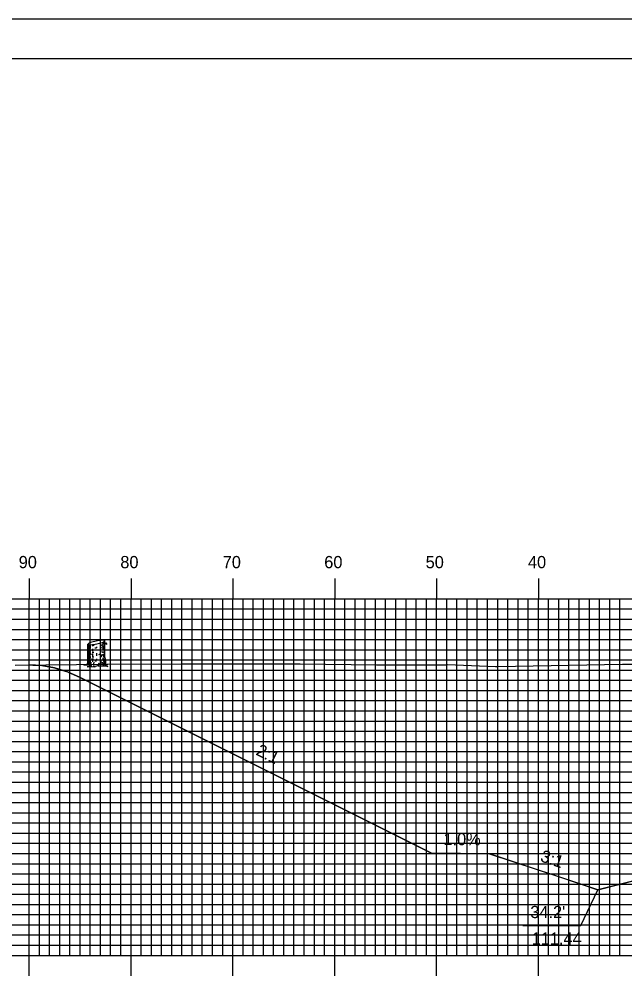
# Model space of a CAD drawing. Extents: x 1767694 to 1768037, y 442591 to 442811.
# Drawn here: x 1767768.5 to 1767827.9, y 442716.2 to 442810.5 of the extents above; entities that cross this region are included whole.
import ezdxf

# ---------------------------------------------------------------- set-up
doc = ezdxf.new("R2010")
doc.units = 0
for name, color, linetype in [('ANNOTATION', 7, 'Continuous'), ('BORDER', 7, 'Continuous'), ('D_Roadway_Centerline', 7, 'Continuous'), ('D_Roadway_SlopeLines', 7, 'Continuous'), ('H_V ANNOTATION', 7, 'Continuous'), ('M_Trees_Conifer_Pay', 7, 'Continuous'), ('MAJOR', 7, 'Continuous'), ('MINOR', 7, 'Continuous'), ('PLOT BOUNDARY', 7, 'Continuous'), ('S_Roadway_Centerline', 7, 'Continuous')]:
    doc.layers.add(name, color=color, linetype=linetype)

msp = doc.modelspace()

# ---------------------------------------------------------------- linework, layer by layer
at = {"layer": 'ANNOTATION'}
msp.add_lwpolyline([(1767817.92, 442721.594), (1767823.612, 442721.594), (1767825.276, 442725.102)], dxfattribs=at)
at = {"layer": 'BORDER'}
msp.add_lwpolyline([(1767709.85, 442596.665), (1768029.85, 442596.665), (1768029.85, 442806.665), (1767709.85, 442806.665)], close=True, dxfattribs=at)
at = {"layer": 'D_Roadway_Centerline'}
msp.add_lwpolyline([(1767769.449, 442747.172), (1767769.818, 442747.152), (1767770.699, 442747.105), (1767771.95, 442746.879), (1767772.422, 442746.733), (1767773.2, 442746.493), (1767774.449, 442745.948), (1767808.936, 442728.705), (1767808.94, 442728.703), (1767814.641, 442728.646), (1767814.645, 442728.646), (1767821.607, 442726.325), (1767825.276, 442725.102), (1767825.277, 442725.103), (1767829.276, 442726.102)], dxfattribs=at)
at = {"layer": 'D_Roadway_SlopeLines'}
for points in [[(1767814.645, 442728.646), (1767808.94, 442728.703), (1767774.449, 442745.948), (1767773.2, 442746.493), (1767771.95, 442746.879), (1767770.699, 442747.105), (1767769.449, 442747.172)], [(1767825.276, 442725.102), (1767814.645, 442728.646)], [(1767839.449, 442728.646), (1767825.276, 442725.102)]]:
    msp.add_lwpolyline(points, dxfattribs=at)
at = {"layer": 'M_Trees_Conifer_Pay'}
for p, q in [((1767775.22, 442747.481), (1767775.22, 442749.203)), ((1767775.267, 442749.165), (1767775.267, 442748.694)), ((1767775.325, 442749.154), (1767775.325, 442749.057)), ((1767775.325, 442748.982), (1767775.325, 442748.778)), ((1767775.451, 442749.146), (1767775.451, 442748.914)), ((1767775.451, 442748.873), (1767775.451, 442748.799)), ((1767775.67, 442749.167), (1767775.67, 442748.999)), ((1767776.076, 442748.935), (1767776.076, 442748.84)), ((1767776.466, 442749.209), (1767776.466, 442749.009)), ((1767776.466, 442748.952), (1767776.466, 442748.863)), ((1767776.695, 442749.405), (1767776.695, 442749.182)), ((1767776.695, 442749.093), (1767776.695, 442749.046)), ((1767776.752, 442748.91), (1767776.701, 442748.85)), ((1767776.812, 442749.466), (1767776.812, 442749.303)), ((1767776.812, 442749.236), (1767776.812, 442749.108)), ((1767776.812, 442748.921), (1767776.812, 442748.585)), ((1767776.884, 442747.891), (1767776.884, 442749.538)), ((1767775.267, 442748.63), (1767775.267, 442748.322)), ((1767775.267, 442748.274), (1767775.267, 442747.782)), ((1767775.325, 442748.721), (1767775.325, 442748.521)), ((1767775.325, 442748.474), (1767775.325, 442748.138)), ((1767775.325, 442748.085), (1767775.325, 442747.949)), ((1767775.451, 442748.396), (1767775.451, 442748.257)), ((1767775.451, 442747.986), (1767775.451, 442747.844)), ((1767775.67, 442748.762), (1767775.67, 442748.525)), ((1767775.67, 442748.28), (1767775.67, 442748.128)), ((1767775.67, 442748.085), (1767775.67, 442747.911)), ((1767776.076, 442748.322), (1767776.076, 442748.247)), ((1767776.076, 442748.223), (1767776.076, 442748.074)), ((1767776.466, 442748.515), (1767776.466, 442748.41)), ((1767776.466, 442748.043), (1767776.466, 442747.897)), ((1767776.695, 442748.711), (1767776.695, 442748.579)), ((1767776.695, 442748.468), (1767776.695, 442748.358)), ((1767776.695, 442748.223), (1767776.695, 442748.081)), ((1767776.812, 442748.548), (1767776.812, 442748.385)), ((1767776.812, 442748.338), (1767776.812, 442748.121)), ((1767776.812, 442748.091), (1767776.812, 442748.016)), ((1767776.812, 442747.976), (1767776.812, 442747.803)), ((1767775.267, 442747.728), (1767775.267, 442747.481)), ((1767775.325, 442747.85), (1767775.325, 442747.471)), ((1767775.451, 442747.582), (1767775.451, 442747.488)), ((1767775.451, 442747.088), (1767775.613, 442747.152)), ((1767775.67, 442747.634), (1767775.67, 442747.481)), ((1767775.888, 442747.024), (1767775.762, 442747.088)), ((1767776.076, 442747.782), (1767776.076, 442747.629)), ((1767776.466, 442747.665), (1767776.466, 442747.576)), ((1767776.695, 442747.854), (1767776.695, 442747.681))]:
    msp.add_line(p, q, dxfattribs=at)
for points in [[(1767776.667, 442748.999), (1767776.636, 442748.914), (1767776.632, 442748.847), (1767776.663, 442748.783)], [(1767776.701, 442749.036), (1767776.737, 442748.962), (1767776.785, 442749.019), (1767776.842, 442749.087), (1767776.935, 442749.281), (1767776.999, 442749.328), (1767777.03, 442749.335)], [(1767776.715, 442748.783), (1767776.752, 442748.91), (1767776.815, 442749.026), (1767776.846, 442749.093), (1767776.915, 442749.24)], [(1767776.93, 442749.269), (1767777.005, 442749.277), (1767777.077, 442749.178)], [(1767775.399, 442748.509), (1767775.393, 442748.604), (1767775.436, 442748.581), (1767775.436, 442748.486)], [(1767776.538, 442748.11), (1767776.55, 442748.033), (1767776.598, 442748.043), (1767776.585, 442748.21)], [(1767776.884, 442747.891), (1767776.935, 442747.629), (1767776.951, 442747.356), (1767777.009, 442747.23), (1767777.145, 442747.2), (1767776.915, 442747.162), (1767776.915, 442747.162), (1767776.92, 442747.115), (1767777.168, 442747.02), (1767776.894, 442747.037), (1767776.538, 442747.057), (1767776.216, 442747.047), (1767776.223, 442747.129), (1767776.075, 442747.047), (1767775.888, 442747.024), (1767775.912, 442746.956), (1767775.644, 442746.999), (1767775.424, 442746.973), (1767775.131, 442746.99), (1767775.42, 442747.047), (1767775.451, 442747.088), (1767775.288, 442747.146), (1767775.051, 442747.156), (1767774.81, 442747.156), (1767775.152, 442747.214), (1767775.193, 442747.294), (1767775.22, 442747.481)], [(1767775.268, 442747.434), (1767775.247, 442747.356), (1767775.226, 442747.261)], [(1767775.346, 442747.413), (1767775.352, 442747.298), (1767775.298, 442747.209), (1767775.288, 442747.146)], [(1767775.508, 442747.44), (1767775.508, 442747.308), (1767775.42, 442747.209)], [(1767775.735, 442747.2), (1767775.802, 442747.294), (1767775.829, 442747.434)], [(1767776.223, 442747.129), (1767776.297, 442747.271), (1767776.307, 442747.372)], [(1767776.474, 442747.498), (1767776.484, 442747.372), (1767776.558, 442747.329)], [(1767776.752, 442747.109), (1767776.737, 442747.247), (1767776.663, 442747.376)], [(1767776.71, 442747.603), (1767776.785, 442747.498), (1767776.789, 442747.325), (1767776.915, 442747.162)], [(1767776.81, 442747.749), (1767776.815, 442747.603), (1767776.863, 442747.535), (1767776.873, 442747.335)]]:
    msp.add_lwpolyline(points, dxfattribs=at)
for centre, radius, start, end in [((1767775.252, 442749.025), 0.0334, 163.94846, 180), ((1767775.252, 442749.025), 0.0334, 180, 196.05154), ((1767775.251, 442749.202), 0.0314, 156.51582, 169.2194), ((1767775.246, 442749.203), 0.0264, 169.2194, 180.03145), ((1767775.242, 442749.203), 0.0226, 180.03145, 191.7194), ((1767775.242, 442749.203), 0.0226, 191.7194, 203.40735), ((1767775.262, 442749.028), 0.0441, 196.05154, 210), ((1767775.271, 442749.193), 0.0527, 146.7194, 156.51582), ((1767775.246, 442749.204), 0.0264, 203.40735, 214.2194), ((1767775.25, 442749.207), 0.0314, 214.2194, 226.92298), ((1767775.278, 442749.037), 0.0624, 210, 228.74941), ((1767775.295, 442749.177), 0.0817, 132.38868, 146.7194), ((1767775.265, 442749.222), 0.0527, 226.92298, 236.7194), ((1767775.28, 442749.247), 0.0817, 236.7194, 251.05013), ((1767775.35, 442749.119), 0.172, 228.74941, 240), ((1767775.409, 442749.052), 0.251, 124.2194, 132.38868), ((1767775.335, 442749.406), 0.251, 251.05013, 259.2194), ((1767775.55, 442749.464), 0.571, 240, 240.33672), ((1767775.719, 442748.597), 0.802, 108.05939, 124.2194), ((1767775.438, 442749.948), 0.802, 259.2194, 275.37941), ((1767775.55, 442749.464), 0.571, 246.85973, 257.98457), ((1767777.076, 442744.435), 5.179, 101.7194, 108.05939), ((1767775.028, 442754.306), 5.179, 275.37941, 281.7194), ((1767776.052, 442753.215), 4.124, 264.6955, 266.73309), ((1767777.076, 442744.435), 5.179, 95.37941, 101.7194), ((1767775.028, 442754.306), 5.179, 281.7194, 288.05939), ((1767776.05, 442752.982), 4.124, 275.78493, 277.05584), ((1767776.052, 442753.215), 4.124, 276.23804, 278.1032), ((1767776.665, 442748.793), 0.802, 79.2194, 95.37941), ((1767776.385, 442750.144), 0.802, 288.05939, 304.2194), ((1767776.553, 442749.697), 0.571, 278.1032, 284.36665), ((1767776.553, 442749.852), 0.571, 284.43166, 292.41325), ((1767776.553, 442749.697), 0.571, 297.0237, 300), ((1767776.768, 442749.335), 0.251, 71.05013, 79.2194), ((1767776.695, 442749.688), 0.251, 304.2194, 312.38868), ((1767776.752, 442749.507), 0.172, 300, 311.25059), ((1767776.752, 442749.352), 0.172, 300, 311.25059), ((1767776.823, 442749.494), 0.0817, 56.7194, 71.05013), ((1767776.809, 442749.564), 0.0817, 312.38868, 326.7194), ((1767776.824, 442749.424), 0.0624, 311.25059, 330), ((1767776.824, 442749.27), 0.0624, 311.25059, 330), ((1767776.839, 442749.518), 0.0527, 46.92298, 56.7194), ((1767776.854, 442749.534), 0.0314, 34.2194, 46.92298), ((1767776.833, 442749.548), 0.0527, 326.7194, 336.51582), ((1767776.84, 442749.415), 0.0441, 330, 343.94846), ((1767776.84, 442749.26), 0.0441, 330, 343.94846), ((1767776.858, 442749.537), 0.0264, 23.40735, 34.2194), ((1767776.852, 442749.539), 0.0314, 336.51582, 349.2194), ((1767776.861, 442749.538), 0.0226, 11.7194, 23.40735), ((1767776.861, 442749.538), 0.0226, 0.03145, 11.7194), ((1767776.857, 442749.538), 0.0264, 349.2194, 0.03145), ((1767776.851, 442749.412), 0.0334, 343.94846, 354.21506), ((1767776.851, 442749.257), 0.0334, 343.94846, 354.21506), ((1767775.252, 442748.578), 0.0334, 163.94846, 180), ((1767775.252, 442748.578), 0.0334, 180, 196.05154), ((1767775.252, 442748.368), 0.0334, 163.94846, 180), ((1767775.252, 442748.368), 0.0334, 180, 196.05154), ((1767775.252, 442748.131), 0.0334, 163.94846, 180), ((1767775.252, 442748.131), 0.0334, 180, 196.05154), ((1767775.252, 442747.933), 0.0334, 163.94846, 180), ((1767775.262, 442748.581), 0.0441, 196.05154, 210), ((1767775.262, 442748.371), 0.0441, 196.05154, 210), ((1767775.262, 442748.134), 0.0441, 196.05154, 210), ((1767775.278, 442748.59), 0.0624, 210, 228.74941), ((1767775.278, 442748.38), 0.0624, 210, 228.74941), ((1767775.278, 442748.143), 0.0624, 210, 228.74941), ((1767775.35, 442748.672), 0.172, 228.74941, 240), ((1767775.35, 442748.462), 0.172, 228.74941, 240), ((1767775.35, 442748.226), 0.172, 228.74941, 240), ((1767775.55, 442749.018), 0.571, 240, 240.33672), ((1767775.55, 442748.808), 0.571, 240, 246.85973), ((1767775.55, 442748.571), 0.571, 240, 246.85973), ((1767775.551, 442749.253), 0.571, 240, 247.05866), ((1767775.55, 442748.808), 0.571, 259.27072, 261.8968), ((1767776.05, 442752.325), 4.124, 261.8968, 263.14738), ((1767776.05, 442752.535), 4.124, 264.08098, 266.66759), ((1767776.05, 442752.088), 4.124, 264.71603, 266.31934), ((1767776.05, 442752.982), 4.124, 268.07512, 270), ((1767776.05, 442752.982), 4.124, 270, 270.35814), ((1767776.05, 442752.325), 4.124, 270, 270.35814), ((1767776.05, 442752.325), 4.124, 273.14934, 275.45691), ((1767776.052, 442752.771), 4.124, 273.70524, 275.95043), ((1767776.05, 442752.535), 4.124, 277.61247, 278.1032), ((1767776.551, 442749.018), 0.571, 278.1032, 286.92962), ((1767776.553, 442749.253), 0.571, 284.44928, 297.04285), ((1767776.551, 442748.571), 0.571, 285.39827, 297.18959), ((1767776.551, 442749.018), 0.571, 297.18959, 300), ((1767776.551, 442748.808), 0.571, 297.18959, 300), ((1767776.75, 442748.672), 0.172, 300, 311.25059), ((1767776.75, 442748.462), 0.172, 300, 311.25059), ((1767776.823, 442748.59), 0.0624, 311.25059, 330), ((1767776.823, 442748.38), 0.0624, 311.25059, 330), ((1767776.839, 442748.581), 0.0441, 330, 343.94846), ((1767776.839, 442748.371), 0.0441, 330, 343.94846), ((1767776.839, 442747.936), 0.0441, 330, 343.94846), ((1767776.849, 442748.578), 0.0334, 343.94846, 354.21506), ((1767776.849, 442748.368), 0.0334, 343.94846, 354.21506), ((1767776.849, 442747.933), 0.0334, 343.94846, 354.21506), ((1767776.85, 442748.813), 0.0334, 343.94846, 354.21506), ((1767775.252, 442747.738), 0.0334, 163.94846, 180), ((1767775.252, 442747.738), 0.0334, 180, 196.05154), ((1767775.252, 442747.517), 0.0334, 163.94846, 180), ((1767775.252, 442747.517), 0.0334, 180, 196.05154), ((1767775.262, 442747.741), 0.0441, 196.05154, 210), ((1767775.262, 442747.52), 0.0441, 196.05154, 210), ((1767775.278, 442747.75), 0.0624, 210, 228.74941), ((1767775.278, 442747.53), 0.0624, 210, 228.74941), ((1767775.35, 442747.832), 0.172, 228.74941, 240), ((1767775.35, 442747.612), 0.172, 228.74941, 240), ((1767775.539, 442748.379), 0.571, 241.23686, 248.02677), ((1767775.55, 442748.177), 0.571, 240, 246.85973), ((1767775.55, 442747.957), 0.571, 240, 244.53138), ((1767776.05, 442751.475), 4.124, 262.44379, 263.51202), ((1767776.05, 442751.891), 4.124, 263.49906, 265.83975), ((1767776.05, 442751.695), 4.124, 267.81166, 270), ((1767776.05, 442751.695), 4.124, 270, 270.13279), ((1767776.05, 442751.695), 4.124, 275.78493, 276.78961), ((1767776.05, 442751.475), 4.124, 277.36842, 278.1032), ((1767776.551, 442747.957), 0.571, 278.1032, 281.63703), ((1767776.551, 442748.177), 0.571, 288.50673, 297.27208), ((1767776.551, 442748.373), 0.571, 289.29072, 300), ((1767776.75, 442748.028), 0.172, 300, 311.25059), ((1767776.75, 442747.612), 0.172, 300, 311.25059), ((1767776.823, 442747.945), 0.0624, 311.25059, 330), ((1767776.823, 442747.53), 0.0624, 311.25059, 330), ((1767776.839, 442747.52), 0.0441, 330, 343.94846), ((1767776.849, 442747.517), 0.0334, 343.94846, 354.21506)]:
    msp.add_arc(centre, radius, start, end, dxfattribs=at)
at = {"layer": 'MAJOR'}
for p, q in [((1767769.45, 442755.669), (1767769.45, 442753.665)), ((1767779.45, 442755.669), (1767779.45, 442753.665)), ((1767789.45, 442755.669), (1767789.45, 442753.665)), ((1767799.45, 442755.669), (1767799.45, 442753.665)), ((1767809.45, 442755.669), (1767809.45, 442753.665)), ((1767819.45, 442755.669), (1767819.45, 442753.665)), ((1767719.45, 442753.665), (1767999.45, 442753.665)), ((1767719.45, 442753.665), (1767999.45, 442753.665)), ((1767769.45, 442718.665), (1767769.45, 442753.665)), ((1767779.45, 442718.665), (1767779.45, 442753.665)), ((1767789.45, 442718.665), (1767789.45, 442753.665)), ((1767799.45, 442718.665), (1767799.45, 442753.665)), ((1767809.45, 442718.665), (1767809.45, 442753.665)), ((1767819.45, 442718.665), (1767819.45, 442753.665)), ((1767719.45, 442748.665), (1767999.45, 442748.665)), ((1767719.45, 442743.665), (1767999.45, 442743.665)), ((1767719.45, 442738.665), (1767999.45, 442738.665)), ((1767719.45, 442733.665), (1767999.45, 442733.665)), ((1767719.45, 442728.665), (1767999.45, 442728.665)), ((1767719.45, 442723.665), (1767999.45, 442723.665)), ((1767719.45, 442718.665), (1767999.45, 442718.665)), ((1767719.45, 442718.665), (1767999.45, 442718.665)), ((1767769.45, 442716.661), (1767769.45, 442718.665)), ((1767779.45, 442716.661), (1767779.45, 442718.665)), ((1767789.45, 442716.661), (1767789.45, 442718.665)), ((1767799.45, 442716.661), (1767799.45, 442718.665)), ((1767809.45, 442716.661), (1767809.45, 442718.665)), ((1767819.45, 442716.661), (1767819.45, 442718.665))]:
    msp.add_line(p, q, dxfattribs=at)
at = {"layer": 'MINOR'}
for p, q in [((1767770.45, 442718.665), (1767770.45, 442753.665)), ((1767771.45, 442718.665), (1767771.45, 442753.665)), ((1767772.45, 442718.665), (1767772.45, 442753.665)), ((1767773.45, 442718.665), (1767773.45, 442753.665)), ((1767774.45, 442718.665), (1767774.45, 442753.665)), ((1767775.45, 442718.665), (1767775.45, 442753.665)), ((1767776.45, 442718.665), (1767776.45, 442753.665)), ((1767777.45, 442718.665), (1767777.45, 442753.665)), ((1767778.45, 442718.665), (1767778.45, 442753.665)), ((1767780.45, 442718.665), (1767780.45, 442753.665)), ((1767781.45, 442718.665), (1767781.45, 442753.665)), ((1767782.45, 442718.665), (1767782.45, 442753.665)), ((1767783.45, 442718.665), (1767783.45, 442753.665)), ((1767784.45, 442718.665), (1767784.45, 442753.665)), ((1767785.45, 442718.665), (1767785.45, 442753.665)), ((1767786.45, 442718.665), (1767786.45, 442753.665)), ((1767787.45, 442718.665), (1767787.45, 442753.665)), ((1767788.45, 442718.665), (1767788.45, 442753.665)), ((1767790.45, 442718.665), (1767790.45, 442753.665)), ((1767791.45, 442718.665), (1767791.45, 442753.665)), ((1767792.45, 442718.665), (1767792.45, 442753.665)), ((1767793.45, 442718.665), (1767793.45, 442753.665)), ((1767794.45, 442718.665), (1767794.45, 442753.665)), ((1767795.45, 442718.665), (1767795.45, 442753.665)), ((1767796.45, 442718.665), (1767796.45, 442753.665)), ((1767797.45, 442718.665), (1767797.45, 442753.665)), ((1767798.45, 442718.665), (1767798.45, 442753.665)), ((1767800.45, 442718.665), (1767800.45, 442753.665)), ((1767801.45, 442718.665), (1767801.45, 442753.665)), ((1767802.45, 442718.665), (1767802.45, 442753.665)), ((1767803.45, 442718.665), (1767803.45, 442753.665)), ((1767804.45, 442718.665), (1767804.45, 442753.665)), ((1767805.45, 442718.665), (1767805.45, 442753.665)), ((1767806.45, 442718.665), (1767806.45, 442753.665)), ((1767807.45, 442718.665), (1767807.45, 442753.665)), ((1767808.45, 442718.665), (1767808.45, 442753.665)), ((1767810.45, 442718.665), (1767810.45, 442753.665)), ((1767811.45, 442718.665), (1767811.45, 442753.665)), ((1767812.45, 442718.665), (1767812.45, 442753.665)), ((1767813.45, 442718.665), (1767813.45, 442753.665)), ((1767814.45, 442718.665), (1767814.45, 442753.665)), ((1767815.45, 442718.665), (1767815.45, 442753.665)), ((1767816.45, 442718.665), (1767816.45, 442753.665)), ((1767817.45, 442718.665), (1767817.45, 442753.665)), ((1767818.45, 442718.665), (1767818.45, 442753.665)), ((1767820.45, 442718.665), (1767820.45, 442753.665)), ((1767821.45, 442718.665), (1767821.45, 442753.665)), ((1767822.45, 442718.665), (1767822.45, 442753.665)), ((1767823.45, 442718.665), (1767823.45, 442753.665)), ((1767824.45, 442718.665), (1767824.45, 442753.665)), ((1767825.45, 442718.665), (1767825.45, 442753.665)), ((1767826.45, 442718.665), (1767826.45, 442753.665)), ((1767827.45, 442718.665), (1767827.45, 442753.665)), ((1767719.45, 442752.665), (1767999.45, 442752.665)), ((1767719.45, 442751.665), (1767999.45, 442751.665)), ((1767719.45, 442750.665), (1767999.45, 442750.665)), ((1767719.45, 442749.665), (1767999.45, 442749.665)), ((1767719.45, 442747.665), (1767999.45, 442747.665)), ((1767719.45, 442746.665), (1767999.45, 442746.665)), ((1767719.45, 442745.665), (1767999.45, 442745.665)), ((1767719.45, 442744.665), (1767999.45, 442744.665)), ((1767719.45, 442742.665), (1767999.45, 442742.665)), ((1767719.45, 442741.665), (1767999.45, 442741.665)), ((1767719.45, 442740.665), (1767999.45, 442740.665)), ((1767719.45, 442739.665), (1767999.45, 442739.665)), ((1767719.45, 442737.665), (1767999.45, 442737.665)), ((1767719.45, 442736.665), (1767999.45, 442736.665)), ((1767719.45, 442735.665), (1767999.45, 442735.665)), ((1767719.45, 442734.665), (1767999.45, 442734.665)), ((1767719.45, 442732.665), (1767999.45, 442732.665)), ((1767719.45, 442731.665), (1767999.45, 442731.665)), ((1767719.45, 442730.665), (1767999.45, 442730.665)), ((1767719.45, 442729.665), (1767999.45, 442729.665)), ((1767719.45, 442727.665), (1767999.45, 442727.665)), ((1767719.45, 442726.665), (1767999.45, 442726.665)), ((1767719.45, 442725.665), (1767999.45, 442725.665)), ((1767719.45, 442724.665), (1767999.45, 442724.665)), ((1767719.45, 442722.665), (1767999.45, 442722.665)), ((1767719.45, 442721.665), (1767999.45, 442721.665)), ((1767719.45, 442720.665), (1767999.45, 442720.665)), ((1767719.45, 442719.665), (1767999.45, 442719.665))]:
    msp.add_line(p, q, dxfattribs=at)
at = {"layer": 'PLOT BOUNDARY'}
msp.add_lwpolyline([(1767693.663, 442590.547), (1768033.663, 442590.547), (1768033.663, 442810.547), (1767693.663, 442810.547)], close=True, dxfattribs=at)
at = {"layer": 'S_Roadway_Centerline'}
msp.add_lwpolyline([(1767768.075, 442747.158), (1767777.122, 442747.25), (1767784.504, 442747.274), (1767796.068, 442747.273), (1767803.561, 442747.18), (1767810.37, 442747.172), (1767810.51, 442747.219), (1767815.229, 442747.02), (1767815.429, 442747.018), (1767827.696, 442747.245), (1767829.183, 442747.258), (1767829.413, 442747.24), (1767833.919, 442747.097), (1767847.208, 442747.09), (1767854.272, 442747.05), (1767863.171, 442746.755), (1767872.529, 442746.462), (1767875.146, 442746.389), (1767891.751, 442746.451)], dxfattribs=at)

# ---------------------------------------------------------------- texts
at = {"layer": 'ANNOTATION'}
for s, rotation, p in [('2:1', 333.43569, (1767791.626, 442738.396)), ('1.0%', 359.42755, (1767810.12, 442729.492)), ('3:1', 341.56356, (1767819.564, 442727.915))]:
    msp.add_text(s, height=1.2, rotation=rotation, dxfattribs=at).set_placement(p)
for s, p in [("34.2'", (1767818.655, 442722.32)), ('111.44', (1767818.789, 442719.72))]:
    msp.add_text(s, height=1.2, dxfattribs=at).set_placement(p)
at = {"layer": 'H_V ANNOTATION'}
for s, p in [('90', (1767768.422, 442756.665)), ('80', (1767778.4, 442756.665)), ('70', (1767788.454, 442756.665)), ('60', (1767798.422, 442756.665)), ('50', (1767808.379, 442756.665)), ('40', (1767818.422, 442756.665))]:
    msp.add_text(s, height=1.2, dxfattribs=at).set_placement(p)

doc.saveas('drawing.dxf')
